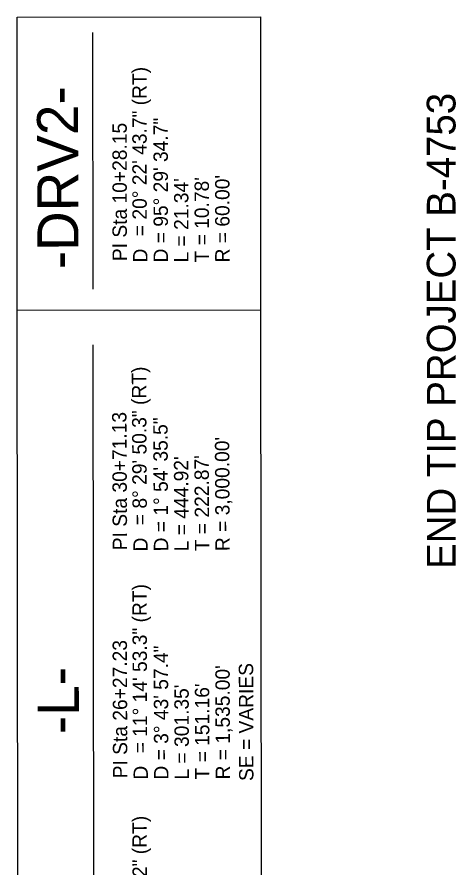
# Model space of a CAD drawing. Extents: x 1373164 to 1374172, y 550391 to 553180.
# Drawn here: x 1373163.6 to 1373377.4, y 551698 to 552112.2 of the extents above; entities that cross this region are included whole.
import ezdxf

# ---------------------------------------------------------------- set-up
doc = ezdxf.new("R2010")
doc.units = 0
doc.layers.add('Exist Structure Minor Pipes RCP 18 Inch Cogo Number', color=7, linetype='Continuous')
doc.layers.add('Exist Structure Minor Pipes RCP 18 Inch Cogo Point CELL', color=7, linetype='Continuous')

msp = doc.modelspace()

# ---------------------------------------------------------------- linework, layer by layer
at = {"layer": 'Exist Structure Minor Pipes RCP 18 Inch Cogo Number'}
for p, q in [((1373163.56, 552112.13), (1373282.24, 552112.24)), ((1373163.69, 551969.36), (1373163.56, 552112.13)), ((1373282.36, 551969.46), (1373282.24, 552112.24)), ((1373200.69, 551979.57), (1373200.57, 552104.67)), ((1373163.69, 551969.36), (1373282.36, 551969.46)), ((1373164.01, 551601.84), (1373163.69, 551969.36)), ((1373282.69, 551601.95), (1373282.36, 551969.46)), ((1373201, 551622.99), (1373200.71, 551952.47))]:
    msp.add_line(p, q, dxfattribs=at)

# ---------------------------------------------------------------- texts
msp.add_text('END TIP PROJECT B-4753', height=14, rotation=90.0131, dxfattribs=at).set_placement((1373377.18, 551843.27))
at = {"layer": 'Exist Structure Minor Pipes RCP 18 Inch Cogo Point CELL'}
for s, height, rotation, p in [('= 20%%d 22\' 43.7" (RT)', 7, 90.0509, (1373226.76, 552005.44)), ('-DRV2-', 20, 90.1622, (1373193.53, 551989.32)), ('PI Sta 10+28.15', 7, 90.0509, (1373217.07, 551993.26)), ('D = 95%%d 29\' 34.7"', 7, 90.0509, (1373237.07, 551992.6)), ("R = 60.00'", 7, 90.0509, (1373267.07, 551992.63)), ("L = 21.34'", 7, 90.0509, (1373247.07, 551992.61)), ("T = 10.78'", 7, 90.0509, (1373257.07, 551992.62)), ('D', 7, 90.0509, (1373227.07, 551992.59)), ('= 8%%d 29\' 50.3" (RT)', 7, 90.2952, (1373226.84, 551864.62)), ('PI Sta 30+71.13', 7, 90.2952, (1373217.2, 551852.39)), ('D = 1%%d 54\' 35.5"', 7, 90.2952, (1373237.2, 551851.82)), ("R = 3,000.00'", 7, 90.2952, (1373267.2, 551851.97)), ("L = 444.92'", 7, 90.2952, (1373247.2, 551851.87)), ("T = 222.87'", 7, 90.2952, (1373257.2, 551851.92)), ('D', 7, 90.2952, (1373227.2, 551851.77)), ('= 11%%d 14\' 53.3" (RT)', 7, 90.1622, (1373226.97, 551753.43)), ('PI Sta 26+27.23', 7, 90.1622, (1373217.3, 551741.22)), ('D = 3%%d 43\' 57.4"', 7, 90.1622, (1373237.3, 551740.6)), ('-L-', 20, 90.1622, (1373193.73, 551762.79)), ("R = 1,535.00'", 7, 90.1622, (1373267.3, 551740.69)), ('SE = VARIES', 7, 90.1622, (1373278.73, 551739.92)), ("L = 301.35'", 7, 90.1622, (1373247.3, 551740.63)), ("T = 151.16'", 7, 90.1622, (1373257.3, 551740.66)), ('D', 7, 90.1622, (1373227.3, 551740.58)), ('= 16%%d 36\' 56.2" (RT)', 7, 90.248, (1373227.05, 551640.49))]:
    msp.add_text(s, height=height, rotation=rotation, dxfattribs=at).set_placement(p)

doc.saveas('drawing.dxf')
